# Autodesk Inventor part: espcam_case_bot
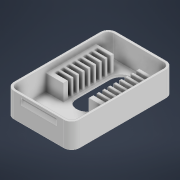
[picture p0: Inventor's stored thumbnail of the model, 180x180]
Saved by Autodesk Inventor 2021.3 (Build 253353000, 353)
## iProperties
Created: 2022-11
Part Number: espcam_case_bot
Material: Generisch
Document SubType Name: Modeling
Designer: markus.rampp
Density: 1 g/cm^3
Appearance: Vorgabe
Author: markus.rampp
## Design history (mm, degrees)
sketch "Skizze1"
  geometry: L1 (14.75, -23)-(-14.75, -23); L2 (-14.75, -23)-(-14.75, 23); L3 (-14.75, 23)-(14.75, 23); L4 (14.75, 23)-(14.75, -23); L5 (0, -32.584)-(0, 34.866); L6 (19.267, 0)-(-23.44, 0); 2 further points
  constraints: 12 end point, 4 point on line, 2 horizontal, 2 parallel, 1 perpendicular, 1 vertical, 2 other
  dimensions: "d0" = 29.5 distance of L1.start L1.end; "d1" = 46 distance of L1.end L2.end
extrude "Extrusion1" new body sketch "Skizze1" distance "d2" = 11; taper "d3" = 0 deg
fillet "Rundung1" dims "d4" = 3.5
feature "Wandung1" dims "d5" = 1
sketch "Skizze2"
  geometry: L1 (0, 23)-(11, 23) reference; L2 (7, 23)-(8.5, 22.2); L3 (8.5, 22.2)-(10, 23); L4 (10, 23)-(7, 23); L5 (11, 23)-(11, 19.5) reference; 1 further point
  constraints: 6 end point, 2 point on line, 1 collinear
  dimensions: "d6" = 3 distance of L3.end L2.start; "d7" = 1.5 horizontal distance of L3.end L2.end; "d8" = 0.8 vertical distance of L3.end L2.end; "d9" = 2.5 distance from line of L5 L2.end
extrude "Extrusion2" cut sketch "Skizze2" stored distance "d10" = 16; taper "d11" = 0 deg
mirror "Spiegeln1"
sketch "Skizze3"
  geometry: L1 (-2.5, 41.5)-(-2.5, 2.5) reference; L2 (-2.5, 38.45)-(5.5, 38.45); L3 (5.5, 38.45)-(5.5, 15.77); L4 (5.5, 15.77)-(-2.5, 15.77); L5 (-2.5, 15.77)-(-2.5, 38.45); L6 (0, 44)-(22.5, 44) reference; 2 further points
  constraints: 8 end point, 2 parallel, 1 horizontal, 1 perpendicular, 1 point on line
  dimensions: "d12" = 22.68 distance of L2.end L3.end; "d13" = 5.55 distance between parallel lines of L6 L2; "d14" = 8 distance of L2.start L2.end
extrude "Extrusion3" join sketch "Skizze3" distance "d15" = 7.4; taper "d16" = 0 deg
chamfer "Fase1" distance "d35" = 0.01; stored, may be unused: second distance "d36" = 2, angle "d37" = 45 deg
sketch "Skizze4"
  geometry: L1 (-0.5, 37.05)-(1, 37.05); L2 (1, 37.05)-(1, 35.55); L3 (1, 35.55)-(-0.5, 35.55); L4 (-0.5, 35.55)-(-0.5, 37.05); L5 (5.5, 38.45)-(-2.5, 38.45) reference; L6 (-2.5, 2.5)-(-2.5, 41.5) reference; 1 further point
  constraints: 8 end point, 2 parallel, 1 horizontal, 1 perpendicular
  dimensions: "d17" = 1.5 distance of L2.end L3.end; "d18" = 1.5 distance of L1.end L2.end; "d19" = 1.4 distance between parallel lines of L5 L1; "d20" = 2 distance between parallel lines of L4 L6
extrude "Extrusion4" cut sketch "Skizze4" stored distance "d21" = 7; taper "d22" = 0 deg
sketch "Skizze5"
  geometry: L1 (0, -7.373)-(1.5, -7.373); L2 (1.5, -7.373)-(1.5, -3); L3 (1.5, -3)-(0, -3); L4 (0, -3)-(0, -7.373); L5 (-19.78, 0)-(2.9, 0) reference; L6 (5.95, -8.4)-(5.95, 2.6) reference; L7 (5.95, -8.4)-(-33.05, -8.4) reference; L8 (-33.05, 2.6)-(-33.05, -8.4) reference; L9 (5.95, 2.6)-(-33.05, 2.6) reference; L10 (1.5, 0)-(1.5, -7.4) reference; L11 (0, 0)-(0, -7.4) reference; L12 (0, -3)-(1.5, -3); L13 (1.5, -3)-(1.5, 0); L14 (1.5, 0)-(0, 0); L15 (0, 0)-(0, -3); 5 further points
  constraints: 16 end point, 4 parallel, 2 collinear, 2 horizontal, 2 perpendicular
  dimensions: "d26" = 3 distance between parallel lines of L5 L3
extrude "Extrusion5" cut sketch "Skizze5" distance "d27" = 7; taper "d28" = 0 deg
sketch "Skizze6"
  geometry: L1 (1, 37.05)-(6.5, 37.05) reference; L2 (1, 35.55)-(6.5, 35.55) reference; L3 (4.5, 37.05)-(3.75, 37.05); L4 (3.75, 37.05)-(3.75, 35.55); L5 (3.75, 35.55)-(4.5, 35.55); L6 (4.5, 35.55)-(4.5, 37.05); L7 (5.5, 38.45)-(5.5, 15.77) reference; L8 (2.6, 35.55)-(5.5, 35.55); L9 (5.5, 35.55)-(5.5, 37.05); L10 (5.5, 37.05)-(2.6, 37.05); L11 (2.6, 37.05)-(2.6, 35.55); L12 (1, 37.05)-(1, 35.55) reference; 8 further points
  constraints: 16 end point, 4 parallel, 2 horizontal, 2 perpendicular, 2 point on line, 1 collinear, 1 midpoint
  dimensions: "d38" = 1.6 distance between parallel lines of L12 L11
extrude "Extrusion6" cut sketch "Skizze6" distance "d29" = 7; taper "d30" = 0 deg
pattern_linear "Rechteckige Anordnung1" dims "d25" = 2.54
mirror "Spiegeln2"
sketch "Skizze7"
  geometry: L1 (0, 0)-(22.5, 0) reference; L2 (11.25, -8)-(11.25, -23); L3 (6.25, -8)-(6.25, -23); L4 (16.25, -23)-(16.25, -8); C1 r 5 at (11.25, -8); A1 r 5 centre (11.25, -8) between (16.25, -8) and (6.25, -8); A2 r 5 centre (11.25, -23) between (6.25, -23) and (16.25, -23); 4 further points
  constraints: 8 end point, 4 point on circle, 4 tangent, 3 centre point, 1 midpoint, 1 parallel, 1 vertical, 1 vertical alignment
  dimensions: "d31" = 10 diameter of C1; "d32" = 8 distance from line of L1 L2.start; "d39" = 5 radius of A1; "d40" = 15 distance of L2.start L2.end
extrude "Extrusion7" cut sketch "Skizze7" distance "d33" = 7; taper "d34" = 0 deg
node "Volumenkörper1"
node "Projizierte Kontur1"
